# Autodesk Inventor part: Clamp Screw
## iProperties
Shininess: 77.0
Length Units: 11269
Angle Units: 11279
Time Units: 11290
Mass Units: 11283
Length Display Precision: 3
Angle Display Precision: 2
Created: 2002-02
Part Number: Clamp Screw
Document SubType Name: Modeling
Designer: ***
Density: 1 g/cm^3
Density: 0.0
Volumn: 0.0
Area: 0.0
PropertySet Name: Model Information
Control State: 0
Master: False
Checked Out: False
Author: ***
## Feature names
1. Revolution1
2. Extrusion1
